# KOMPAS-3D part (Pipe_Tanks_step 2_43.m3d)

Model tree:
1. X Axis
2. Y Axis
3. Z Axis  (labels: T-Bend Dn 50; Pipe Dn 50)
     Òîëùèíà ñòåíêè 1 = 1

Referenced files in C:\Documents and Settings\kashirsky\Мои документы\Camtasia Studio\Pipelines3D\Tanks\: Tanks_step 2.a3d
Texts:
  Pipe Dn 50
  Steel ASTM A295
  Three Point Plane
  Plane at Angle
  Line and Point Plane
  Axis through Two Vertices
  Axis of Feature
  Axis of Conical Surface
  Axis through Edge
  Trim by Surface
  Trim by Sketch
  Feature with No History
  Intersection Axis of Two Planes
  Two Line Plane
  Line and Face Plane
  Bend by line
  Hole in sheet body
  Cut in sheet body
  Point in CM
  Linear Dimension from Line to Point
  Surface Finish Symbol
  Geometric Tolerance Symbol
  Leader #1
  Leader #2
  Leader #3
  Shape Deviations and Datum
  Node point number
  Mark of coordination axis
  Node point designation
  Mark/Reference designation with leader
  Mark/reference designation on line
  Mark/Reference designation without leader
  T-Bend Dn 50
  Plane of section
